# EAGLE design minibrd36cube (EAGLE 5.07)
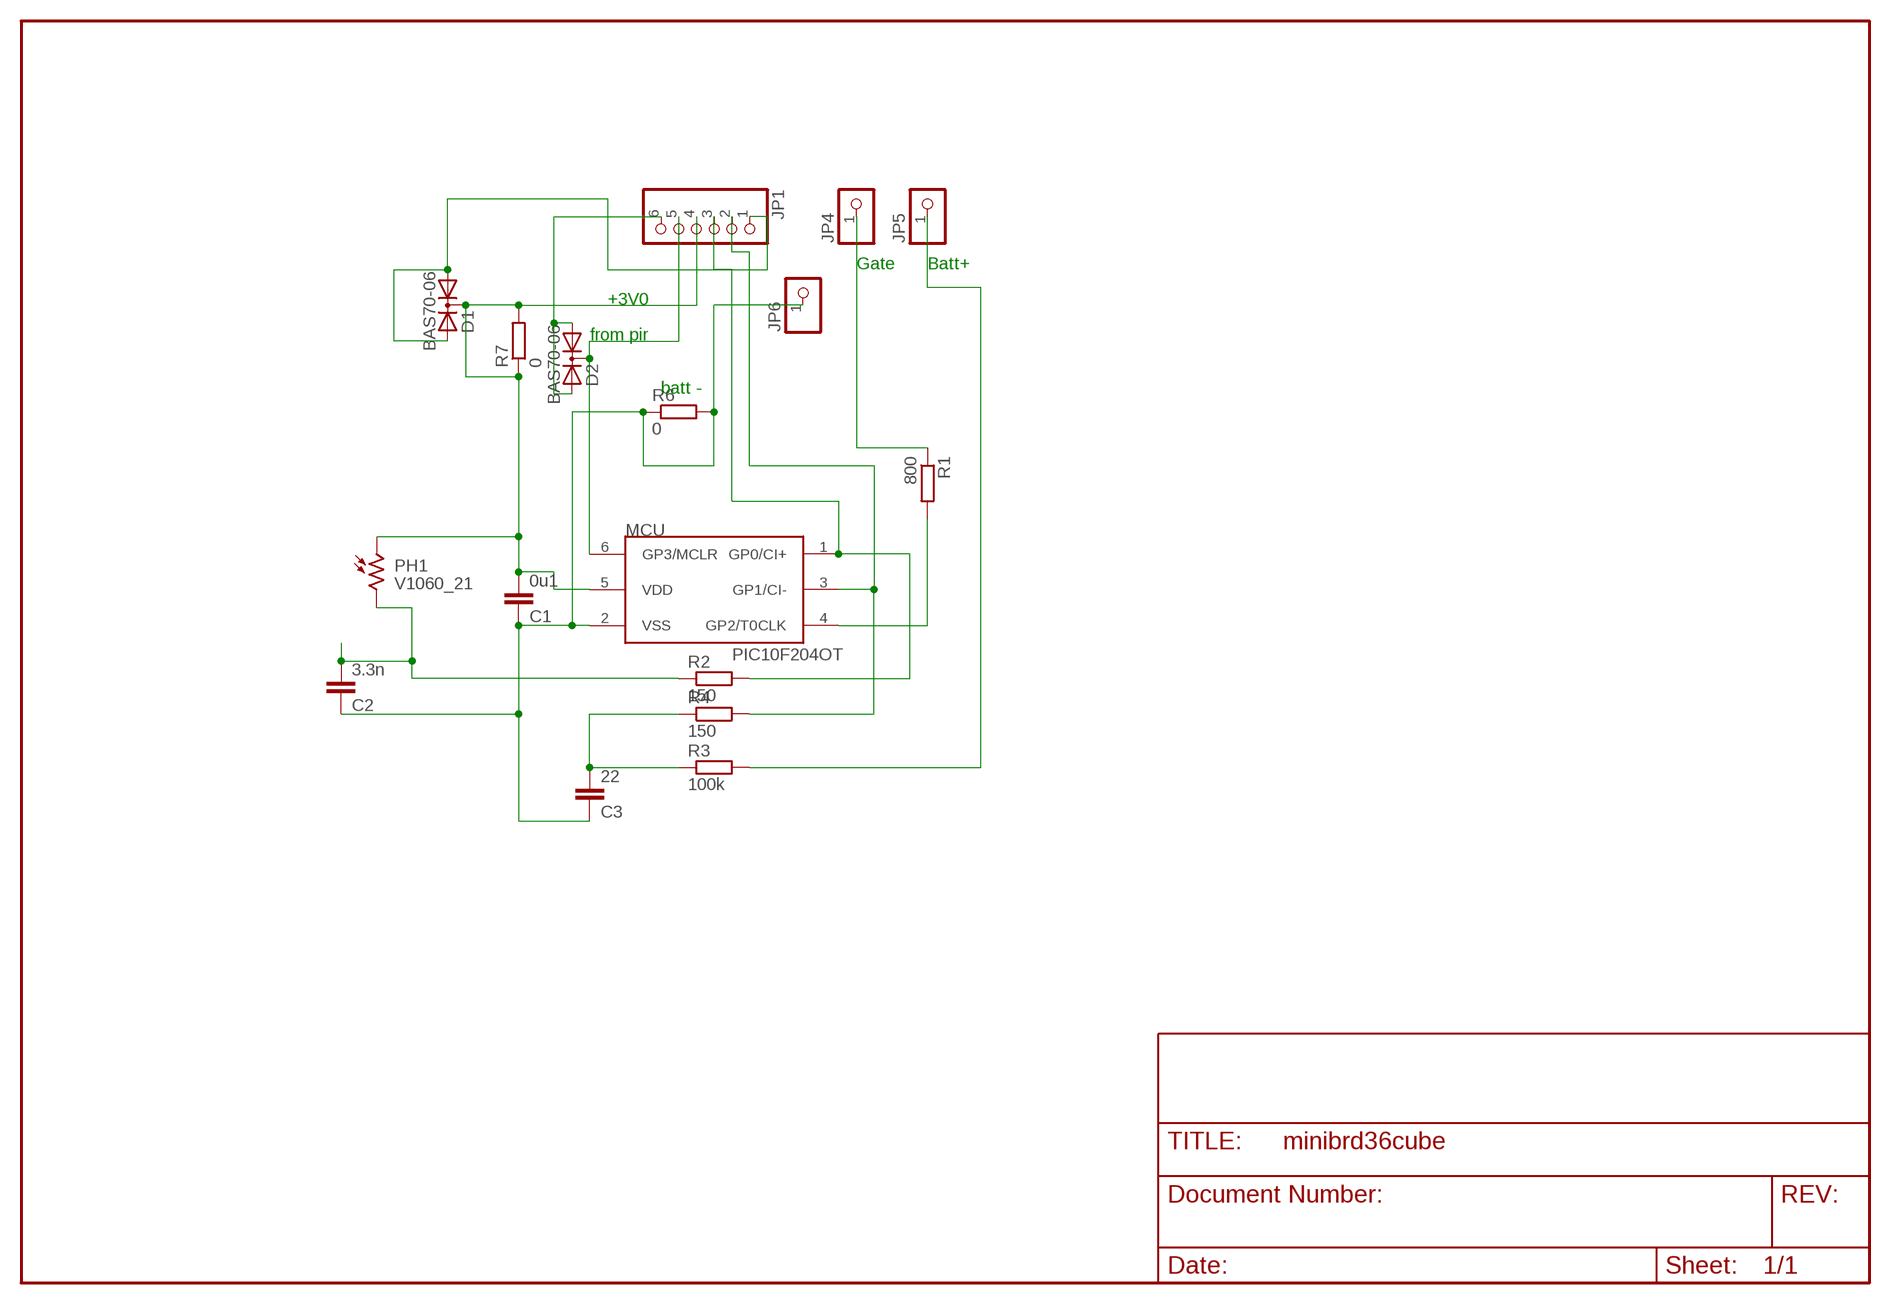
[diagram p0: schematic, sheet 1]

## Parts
C1  0u1  C-EUC1206  [C1206]
C2  3.3n  C-EUC1206  [C1206]
C3  22  C-EUC1206  [C1206]
D1  BAS70-06  [SOT23]
D2  BAS70-06  [SOT23]
JP1  PINHD-1X6  [1X06BOX]
JP4  PINHD-1X1  [1X01]
JP5  PINHD-1X1  [1X01]
JP6  PINHD-1X1  [1X01]
MCU  PIC10F204OT  [SOT23-6]
PH1  V1060_21  [TO-5_V10]
R1  800  R-EU_R1206  [R1206]
R2  150  R-EU_R1206  [R1206]
R3  100k  R-EU_R1206  [R1206]
R4  150  R-EU_R1206  [R1206]
R6  0  R-EU_R1206  [R1206]
R7  0  R-EU_R1206  [R1206]

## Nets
N$1: JP4.1 R1.1
N$2: C2.2 PH1.2 R2.1
N$3: D1.1(A1) D1.2(A2) JP1.1
N$4: JP1.3 MCU.1(GP0/CI+) R2.2
N$5: MCU.4(GP2/T0CLK) R1.2
N$7: C3.2 R3.1 R4.1
N$8: JP1.2 MCU.3(GP1/CI-) R4.2
N$9: D2.1(A1) D2.2(A2) JP1.6
PIR: D2.3(C) JP1.5 MCU.6(GP3/MCLR)
V3: C1.2 D1.3(C) JP1.4 MCU.5(VDD) PH1.1 R7.1 R7.2
V+: JP5.1 R3.2
V-: C1.1 C2.1 C3.1 JP6.1 MCU.2(VSS) R6.1 R6.2

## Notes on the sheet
- Gate | Batt+
- +3V0
- from pir
- batt -

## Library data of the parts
C1-C3 = rcl:C-EU: CAPACITOR, European symbol
D1 D2 = diode:BAS70-06: Silicon Schottky Diodes General-purpose diode for high-speed switching
JP1 = pinhead:PINHD-1X6: PIN HEADER
JP4-JP6 = pinhead:PINHD-1X1: PIN HEADER
MCU = microchip-3:PIC10F2*: uPC nW 0,25/0,5k Program Flash memory Comparator
PH1 = photo-elements:?1060*: Sensor Street Light control
R1-R4 R6 R7 = rcl:R-EU_: RESISTOR, European symbol

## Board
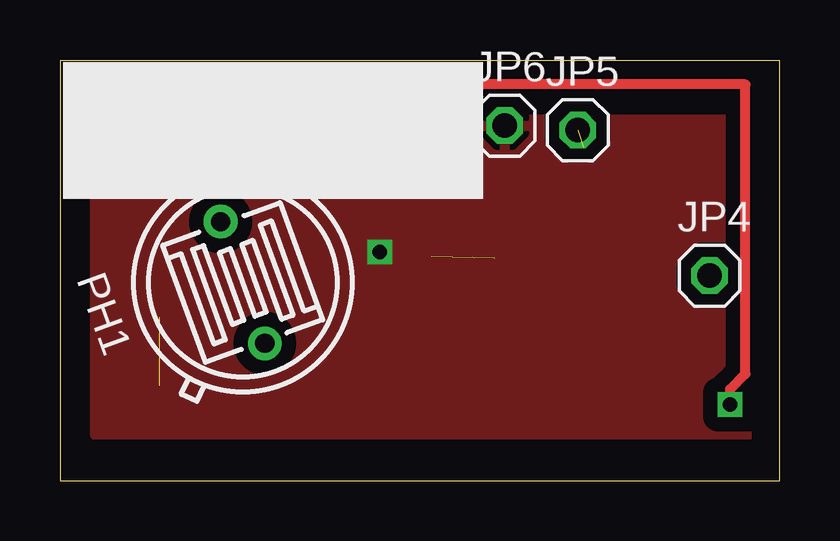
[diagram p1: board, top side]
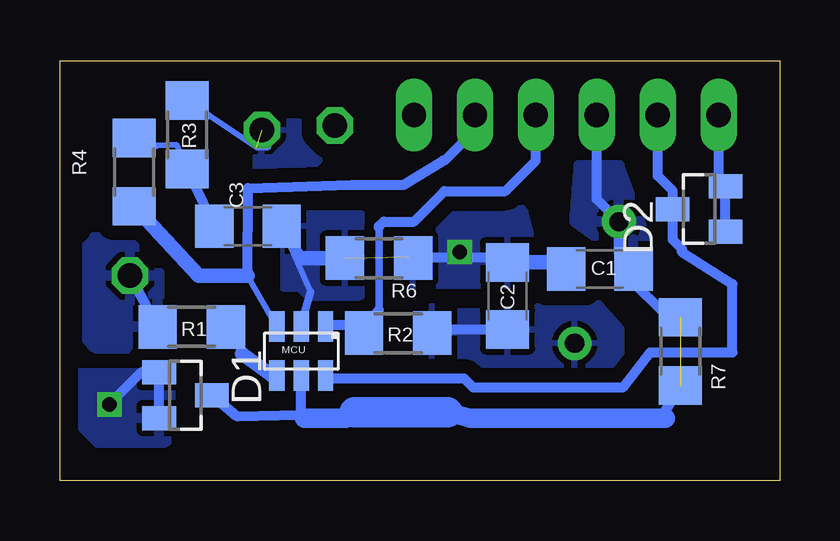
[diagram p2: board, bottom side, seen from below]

Size 30 x 17.5 mm. Coordinates in mm from the lower left corner, seen from the top.
Outline: 0,0 30,0 30,17.5 0,17.5 0,0
Copper layers (1*16): Top 0.035mm / dielectric 1.5mm / Bottom 0.035mm
Design rules "default": minimum track width 10mil, minimum drill 24mil, track to track 8mil, track to pad 8mil, pad to pad 8mil, via to via 8mil, smd to smd 8mil, copper to edge 1mil, drill to drill 8mil, minimum pad ring 10mil, minimum via ring 8mil, stop-mask expansion 4mil, vias tented up to drill 0mil, thermal gap 10mil

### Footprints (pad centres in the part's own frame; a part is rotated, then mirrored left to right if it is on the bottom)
C1206 = smd 1.6 x 1.8: 1 -1.4,0; 2 1.4,0
SOT23 = smd 1 x 1.4: 1 -0.95,-1.1; 2 0.95,-1.1; 3 0,1.1
1X06BOX = drill 1.016 long: 1 -6.35,0; 2 -3.81,0; 3 -1.27,0; 4 1.27,0; 5 3.81,0; 6 6.35,0
1X01 = drill 1.016 octagon: 1 0,0
SOT23-6 = smd 0.635 x 1.27: 1 -1.016,-1.016; 2 0,-1.016; 3 1.016,-1.016; 4 1.016,1.016; 5 0,1.016; 6 -1.016,1.016
TO-5_V10 = drill 0.8 pad 1.4 round: 1 -2.7,0; 2 2.7,0
R1206 = smd 1.6 x 1.803: 1 -1.422,0; 2 1.422,0

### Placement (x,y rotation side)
C1  7.49,8.82 0 bottom
C2  11.34,7.69 270 bottom
C3  22.16,10.6 180 bottom
D1  24.77,3.56 270 bottom
D2  3.36,11.32 90 bottom
JP1  8.89,15.24 180 top
JP4  27.08,8.54 0 top
JP5  21.59,14.61 0 top
JP6  18.54,14.8 0 top
MCU  19.94,5.4 180 bottom
PH1  7.62,8.26 290 top
R1  24.5,6.41 0 bottom
R2  15.9,6.15 180 bottom
R3  24.7,14.41 90 bottom
R4  26.91,12.85 270 bottom
R6  16.7,9.27 0 bottom
R7  4.14,5.39 270 bottom

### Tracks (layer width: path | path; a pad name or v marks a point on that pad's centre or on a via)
N$1
  Bottom 0.406: R1.1 JP4.1
  pour Bottom (isolate 0.61): 25.84,6.79 25.84,9.02 25.84,9.97 26.04,10.16 28.57,10.16 28.57,10.1 28.89,9.78 28.89,5.87 28.54,5.52 26.19,5.52 26.1,5.62
N$2
  Bottom 0.406: 11.49,6.03 11.49,6.29 C2.2 14.41,6.29 14.41,6.15 R2.1
  pour Bottom (isolate 0.61, rank 2): 8,7.94 9.78,7.94 10.22,7.05 13.27,7.05 15.11,7.49 15.24,4.57 7.24,4 6.6,4.51 6.6,6.35
N$3  (via drill 0.6)
  Top 0.406: v27.94,3.17 27.94,3.81 28.57,4.45 28.57,16.51 17.14,16.51 JP1.1
  Bottom 0.406: D1.2 D1.1 26.61,4.51 v27.94,3.17
  pour Bottom (isolate 0.61, rank 2): 25.4,5.08 28.8,5.08 29.05,4.83 29.05,2.19 28.45,1.59 25.62,1.59 25.34,1.87
N$4
  Bottom 0.305: 16.7,7.11 16.7,10.54
  Bottom 0.406: 17.18,6.57 17.27,6.48 18.8,6.48 18.92,6.35 MCU.1 | 17.18,6.57 16.7,7.11 | 17.18,6.57 | R2.2 17.32,6.27 17.18,6.57 | JP1.3 10.16,13.34 11.43,12.06 13.97,12.06 15.24,10.79 16.51,10.79 16.7,10.6 16.7,10.54
N$5
  Bottom 0.254: MCU.4 21.17,4.4 | 22.41,5.29 R1.2
  Bottom 0.61: 21.17,4.4 22.41,5.29
N$7
  Bottom 0.254: R3.1 25.14,13.98 25.96,13.95 R4.1
  Bottom 0.406: C3.2 R3.1
N$8
  Bottom 0.254: MCU.3 22.17,8.55
  Bottom 0.406: 22.17,8.55 22.16,12.19 17.84,12.32 15.68,12.32 14.03,13.34 13.97,13.34 12.7,14.61 JP1.2
  Bottom 0.61: 22.17,8.55 24.23,8.55 R4.2
N$9
  Bottom 0.406: D2.1 D2.2 2.54,12.27 JP1.6
PIR
  Bottom 0.406: MCU.6 18.92,4.25 13.14,4.25 12.76,3.87 6.54,3.87 5.4,5.33 1.97,5.33 1.97,8.19 4.06,9.53 4.06,9.65 4.46,10.04 D2.3 4.46,12.08 5.08,12.7 JP1.5
V3  (1 unrouted)
  Bottom 0.406: 19.94,2.73 MCU.5 | 19.81,2.6 19.94,2.73 | 4.76,2.6 4.89,2.73 R7.2 | R7.1 4.28,6.88 4.83,6.99 6.09,8.25 C1.2 6.7,9.43 PH1.1 7.62,11.72 JP1.4 | D1.3 22.61,2.67 19.94,2.73
  Bottom 0.813: 4.76,2.6 12.89,2.6 13.84,2.86 | 17.72,2.86 18.1,2.6 19.81,2.6
  Bottom 1.27: 13.84,2.86 17.72,2.86
  pour Bottom: 8.38,13.14 8.57,10.79 6.79,9.53 5.33,9.59 6.67,13.14
V+  (1 unrouted)
  Bottom 0.254: 21.32,13.9 21.82,13.9 R3.2
  pour Bottom (isolate 0.61): 19.05,14.92 21.84,14.99 21.84,12.26 20.38,12.13 18.22,14.29
V-  (via drill 0.6)  (1 unrouted)
  Bottom 0.254: 19.55,7.88 C3.1 | MCU.2 19.88,6.73
  Bottom 0.305: 19.88,6.73 19.55,7.88
  Bottom 0.406: 19.94,9.27 20,9.33 C3.1 | C2.1 11.29,9.1 11.24,9.14 11.38,9.29 15.45,9.29 | C1.1 8.96,9.2 9.07,9.1 | 15.45,9.29 15.43,9.27 R6.2 | 15.45,9.29 15.49,9.34
  Bottom 0.61: 19.94,9.27 R6.1 | 9.07,9.1 C2.1
  other vias: 13.34,9.53
  pour Bottom (isolate 0.61): 11.37,12.13 12.76,12.13 13.27,12.06 14.67,10.67 14.92,10.67 15.75,9.84 15.75,8.13 10.35,8.13 10.35,10.22 10.6,11.24
  pour Bottom (isolate 0.406): 17.4,11.11 20.19,11.11 20.7,10.6 20.7,8 20.07,8 19.68,7.62 17.59,7.62 17.4,7.68
  pour Top (isolate 0.61): 1.71,15.05 28.7,15.05 28.7,1.91 1.46,1.91 1.46,14.35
